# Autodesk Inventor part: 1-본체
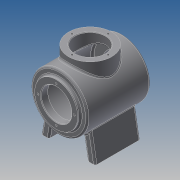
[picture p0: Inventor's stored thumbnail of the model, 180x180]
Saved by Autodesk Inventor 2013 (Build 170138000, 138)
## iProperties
Created: 2015-01
Part Number: 1-본체
Material: Generic
Document SubType Name: Modeling
Designer: kb543
Density: 1 g/cm^3
Author: kb543
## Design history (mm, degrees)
sketch "스케치1"
  geometry: L1 (-62, 0)-(60, 0); L2 (-62, 0)-(-62, 38); L3 (-62, 38)-(-57, 38); L4 (-57, 38)-(-57, 50); L5 (-57, 50)-(55, 50); L6 (55, 50)-(55, 38); L7 (55, 38)-(60, 38); L8 (60, 38)-(60, 0); L9 (-62, 27)-(-50, 27); L10 (-50, 27)-(-50, 45); L11 (-50, 45)-(47, 45); L12 (47, 45)-(47, 27); L13 (47, 27)-(60, 27); 2 further points
  constraints: 26 end point, 6 perpendicular, 5 parallel, 3 point on line, 1 coincident, 1 collinear, 1 horizontal
  dimensions: "d0" = 100 diameter of L5 L1; "d2" = 76 diameter of L3 L1; "d3" = 5 distance of L2.end L3.end; "d4" = 62 distance from line of point (0, 0) L2; "d5" = 60 distance from line of L8 point (0, 0); "d6" = 76 diameter of L7 L1 (= d2); "d7" = 5 distance of L6.end L7.end (= d3); "d10" = 54 diameter of L9 L1; "d11" = 54 diameter of L13 L1 (= d10); "d12" = 97 distance between parallel lines of L12 L10; "d13" = 7 distance between parallel lines of L10 L4; "d14" = 90 diameter of L11 L1
revolve "회전1" stored, may be unused: angle "d9" = 90 deg
revolve "회전2" stored, may be unused: angle "d15" = 90 deg
node "작업 평면2"
sketch "스케치4"
  geometry: L1 (72, 20)-(-4, 20) reference; C1 r 38 at (34, -42); 1 further point
  constraints: 1 centre point, 1 vertical alignment
  dimensions: "d34" = 62 distance from line of C1.centre L1; "d35" = 76 diameter of C1
extrude "돌출2" join sketch "스케치4" stored distance "d36" = 80; taper "d37" = 0 deg
hole "구멍1" diameter "d40" = 54; stored, may be unused: countersink angle "d44" = 90 deg, drill point angle "d46" = 118 deg; dims "d38" = 10, "d39" = 10, "d41" = 6, "d42" = 4, "d43" = 2, "d45" = 8
sketch "스케치5"
  geometry: C1 r 27 at (0, 0) reference; 5 further points
  constraints: 1 vertical alignment, 5 other
  dimensions: "d47" = 32 distance of C1.centre point (0, 32); "d50" = 360 deg dimension on C1.centre point (0, 32) (derived)
hole "구멍2" sketch "스케치5" at (0, 32), (-32, 0), (0, -32), (32, 0) diameter "d52" = 3.242; stored, may be unused: countersink angle "d56" = 90 deg, drill point angle "d58" = 118 deg; dims "d53" = 8, "d54" = 4, "d55" = 2, "d57" = 10
sketch "스케치6"
  geometry: C1 r 27 at (0, 0) reference; 4 further points
  constraints: 1 vertical alignment, 5 other
  dimensions: "d59" = 32 distance of C1.centre point (0, 32); "d62" = 360 deg dimension on C1.centre point (0, 32) (derived)
hole "구멍3" sketch "스케치6" at (0, 32), (-32, 0), (0, -32), (32, 0) diameter "d64" = 3.242; stored, may be unused: countersink angle "d68" = 90 deg, drill point angle "d70" = 118 deg; dims "d65" = 8, "d66" = 4, "d67" = 2, "d69" = 10
node "작업 평면3"
node "작업 평면5"
  node "작업 평면4"
sketch "스케치8"
  geometry: L1 (-37, 62)-(39, 62) reference; L2 (-26, 6)-(28, 6); L3 (28, 6)-(28, -6); L4 (28, -6)-(-26, -6); L5 (-26, -6)-(-26, 6); L6 (-26, 6)-(28, -6); L7 (28, 6)-(-26, -6); 5 further points
  constraints: 12 end point, 4 midpoint, 2 horizontal alignment, 2 parallel, 1 horizontal, 1 perpendicular, 1 vertical alignment
  dimensions: "d75" = 54 distance of L2.start L2.end; "d77" = 12 distance of L4.end L2.start
chamfer "모따기1" distance "d82" = 1; stored, may be unused: second distance "d83" = 2, angle "d84" = 45 deg
chamfer "모따기2" distance "d85" = 1; stored, may be unused: second distance "d86" = 2, angle "d87" = 45 deg
chamfer "모따기3" distance "d88" = 1; stored, may be unused: second distance "d89" = 2, angle "d90" = 45 deg
fillet "모깎기1" dims "d91" = 3
extrude "돌출3" join sketch "스케치8" stored distance "d93" = 80; taper "d94" = 0 deg
node "작업 평면6"
sketch "스케치10"
  geometry: L1 (-6, -28)-(-6, 26) reference; L2 (-6, 26)-(6, 26) reference; 4 further points
  constraints: 2 midpoint, 1 horizontal alignment, 1 vertical alignment, 1 other
feature "엠보싱3" sketch "스케치10" dims "d0" = 100, "d2" = 76, "d3" = 5, "d4" = 62, "d5" = 60, "d6" = 76 (= d2), "d7" = 5 (= d3), "d10" = 54, "d11" = 54 (= d10), "d12" = 97, "d13" = 7, "d14" = 90, "d96" = 0.5, "d97" = 0
node "작업 평면7"
sketch "스케치11"
  geometry: L1 (-39.336, -30.865)-(-48, -80); L2 (-48, -80)-(-34, -80); L3 (-34, -80)-(-27.282, -41.901); L4 (27.282, -41.901)-(34, -80); L5 (34, -80)-(48, -80); L6 (48, -80)-(39.336, -30.865); L7 (0, 50)-(0, -50); A1 r 50 centre (0, 0) between (-39.336, -30.865) and (-27.282, -41.901) reference; 1 further point
  constraints: 14 end point, 6 point on circle, 3 collinear, 1 horizontal, 1 midpoint, 1 parallel, 1 perpendicular, 1 other
  dimensions: "d98" = 80 distance from line of L2 point (0, 0); "d99" = 14 distance of L1.end L2.end; "d100" = 100 deg angle of L2 L1; "d101" = 96 distance of L5.end L1.end; "d102" = 80 deg angle of L5 L4
extrude "돌출4" join sketch "스케치11" stored distance "d103" = 80; taper "d104" = 0 deg
fillet "모깎기3" dims "d105" = 3
fillet "모깎기4" dims "d106" = 3
node "솔리드1"
mirror "대칭1"
other parameters: "d74" = 2, "d95" = 0.5
